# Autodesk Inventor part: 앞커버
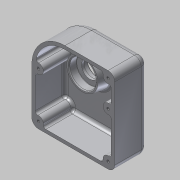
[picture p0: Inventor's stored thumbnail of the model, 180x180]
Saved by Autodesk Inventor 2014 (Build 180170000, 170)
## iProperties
Created: 2015-10
Part Number: 앞커버
Material: 알루미늄 6061
Document SubType Name: Modeling
Designer: mduedu
Density: 2.71 g/cm^3
Mass: 307.08 g
Surface Area: 494.818 cm^2
Volume: 113.314 cm^3
Appearance: 알루미늄 - 평지
Author: mduedu
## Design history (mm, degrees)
sketch "스케치1"
  geometry: L1 (0, 40)-(60, 40); L2 (60, 40)-(60, -63); L3 (60, -63)-(-40, -63); L4 (-40, -63)-(-40, 0); A1 r 40 centre (0, 0) between (0, 40) and (-40, 0); 1 further point
  constraints: 8 end point, 2 point on circle, 2 tangent, 1 centre point, 1 coincident, 1 horizontal, 1 parallel, 1 perpendicular, 1 vertical
  dimensions: "d0" = 40 radius of A1; "d1" = 103 distance of L1.end L2.end; "d2" = 100 distance of L2.end L3.end
extrude "돌출2" new body sketch "스케치1" distance "d8" = 40; taper "d9" = 0 deg
fillet "모깎기3" dims "d10" = 8
fillet "모깎기4" dims "d11" = 8
feature "쉘2" dims "d12" = 4
sketch "스케치2"
  geometry: C1 r 21.5 at (32, 55); 1 further point
  constraints: 1 centre point, 1 coincident
  dimensions: "d13" = 43 diameter of C1
extrude "돌출3" join sketch "스케치2" distance "d14" = 15; taper "d15" = 0 deg
hole "구멍1" diameter "d18" = 32; stored, may be unused: countersink angle "d22" = 90 deg, drill point angle "d24" = 0 deg; dims "d16" = 10, "d17" = 10, "d19" = 6, "d20" = 4, "d21" = 2, "d23" = 9
hole "구멍2" diameter "d27" = 20; stored, may be unused: countersink angle "d31" = 90 deg, drill point angle "d33" = 0 deg; dims "d25" = 10, "d26" = 10, "d28" = 6, "d29" = 4, "d30" = 2, "d32" = 3
hole "구멍3" diameter "d36" = 25; stored, may be unused: countersink angle "d40" = 90 deg, drill point angle "d42" = 0 deg; dims "d34" = 10, "d35" = 10, "d37" = 6, "d38" = 4, "d39" = 2, "d41" = 3
chamfer "모따기1" distance "d43" = 1; stored, may be unused: second distance "d44" = 2, angle "d45" = 45 deg
feature "면 기울기1" dims angle "d46" = 10 deg
sketch "스케치3"
  geometry: L1 (-40, 0)-(-40, -55) reference; L2 (60, -55)-(60, 32) reference; L3 (-40, 0)-(60, 0); C1 r 6 at (52, 32); C2 r 6 at (52, -55); C3 r 6 at (-32, -55); C4 r 6 at (52, 0); C5 r 6 at (-32, 0); A1 r 8 centre (52, 32) between (60, 32) and (52, 40) reference; A2 r 8 centre (52, -55) between (52, -63) and (60, -55) reference; A3 r 8 centre (-32, -55) between (-40, -55) and (-32, -63) reference; 1 further point
  constraints: 5 centre point, 4 equal radius, 3 coincident, 3 point on line, 2 end point, 2 vertical alignment, 1 perpendicular
  dimensions: "d47" = 6 radius of C1
extrude "돌출4" join sketch "스케치3" stored distance "d49" = 15; taper "d50" = 0 deg
fillet "모깎기5" dims "d51" = 3
fillet "모깎기6" dims "d52" = 3
sketch "스케치4"
  geometry: A1 r 6 centre (-32, 0) between (-32.667, -5.963) and (-31.833, 5.998) reference; A2 r 6 centre (52, 32) between (46.037, 32.667) and (52.667, 26.037) reference; A3 r 6 centre (52, 0) between (52.667, 5.963) and (52.667, -5.963) reference; A4 r 6 centre (52, -55) between (52.667, -49.037) and (46.037, -55.667) reference; A5 r 6 centre (-32, -55) between (-26.037, -55.667) and (-32.667, -49.037) reference; 6 further points
  constraints: 5 coincident
hole "구멍4" sketch "스케치4" at (-32, 0), (52, 32), (52, 0), (52, -55), (-32, -55) diameter "d53" = 3.242; stored, may be unused: countersink angle "d57" = 90 deg, drill point angle "d59" = 118 deg; dims "d54" = 12, "d55" = 4, "d56" = 2, "d58" = 14
sketch "스케치5"
  geometry: L1 (-52, -63)-(32, -63) reference; L2 (-60, 32)-(-60, -55) reference; 2 further points
  constraints: 1 other
  dimensions: "d60" = 20 distance from line of point (-10, -43) L1; "d61" = 50 distance from line of point (-10, -43) L2
feature "엠보싱1" sketch "스케치5" dims "d13" = 43, "d62" = 0.5, "d63" = 0
fillet "모깎기7" dims "d64" = 0.3
node "솔리드2"
